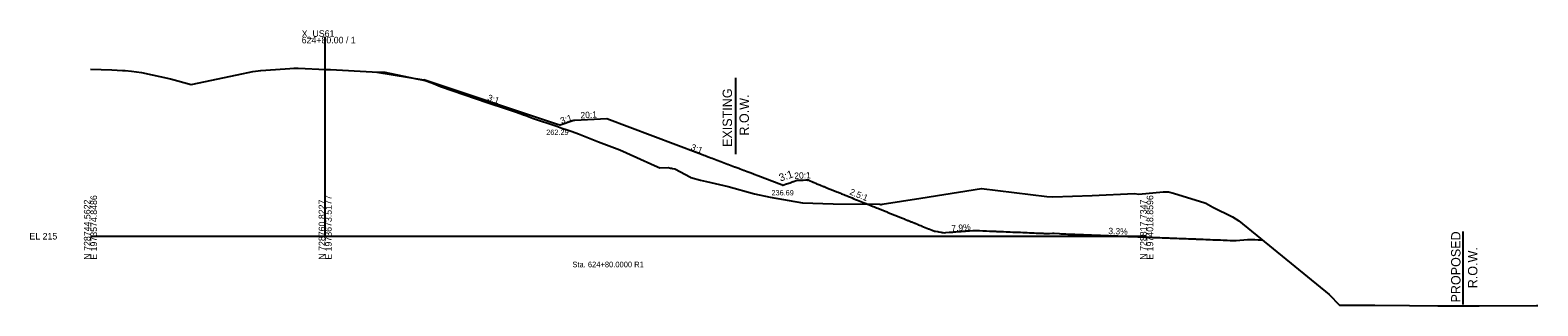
# Model space of a CAD drawing. Extents: x -26 to 630, y -39 to 9098.
# Drawn here: x -26 to 617, y 1970 to 2088 of the extents above; entities that cross this region are included whole.
import ezdxf

# ---------------------------------------------------------------- set-up
doc = ezdxf.new("R2010")
doc.units = 0
for name, color, linetype in [('CONST_DCH', 7, 'Continuous'), ('Default', 7, 'Continuous'), ('Draft_XS_Grid', 7, 'Continuous'), ('Draft_XS_Text', 7, 'Continuous'), ('DTM_X_GROUND', 7, 'Continuous'), ('X_DTM_CONTOURS_MAJOR', 7, 'Continuous'), ('XS_CELL', 7, 'Continuous'), ('XS_P_GROUND', 7, 'Continuous'), ('XS_P_ROW', 7, 'Continuous'), ('XS_P_TX_DCH', 7, 'Continuous'), ('XS_P_TX_FS_BS', 7, 'Continuous'), ('XS_X_ROW', 7, 'Continuous')]:
    doc.layers.add(name, color=color, linetype=linetype)

msp = doc.modelspace()

# ---------------------------------------------------------------- linework, layer by layer
at = {"layer": 'DTM_X_GROUND'}
msp.add_lwpolyline([(0, 2071.16), (9.05, 2070.86), (13.72, 2070.7), (14.81, 2070.61), (17.45, 2070.4), (21.74, 2069.84), (34.08, 2067.05), (42.91, 2064.69), (62.57, 2068.81), (69.11, 2070.18), (72.62, 2070.65), (74.77, 2070.8), (84.88, 2071.51), (86.59, 2071.57), (88.5, 2071.64), (100.31, 2071.11), (102.28, 2071.02), (120, 2070.06), (123.2, 2069.89), (123.41, 2069.89), (125.46, 2069.96), (138.9, 2067.09), (141.96, 2066.49), (143.09, 2066.2), (146.2, 2065.11), (149.2, 2063.86), (168.97, 2057.02), (177.64, 2054.14), (180.66, 2053.14), (183.53, 2052.18), (184.51, 2051.79), (185.52, 2051.39), (188.35, 2050.27), (198.73, 2046.96), (200.81, 2046.05), (202.73, 2045.42), (205.27, 2044.57), (207.88, 2043.65), (216.5, 2040.18), (225.6, 2036.84), (232.83, 2033.61), (240.25, 2030.11), (242.57, 2029.22), (246.18, 2029.32), (247.06, 2029.05), (247.07, 2029.05), (247.11, 2029.04), (247.16, 2029.04), (247.39, 2029), (247.49, 2028.99), (247.93, 2028.93), (249.01, 2028.77), (255.59, 2025.24), (255.81, 2025.09), (259.97, 2023.96), (262.44, 2023.32), (271.66, 2021.21), (282.93, 2018.13), (289.56, 2016.68), (303.36, 2014.22), (316.5, 2013.77), (336.25, 2013.6), (336.7, 2013.49), (336.92, 2013.56), (337.32, 2013.61), (353.8, 2016.2), (379.6, 2020.4), (407.41, 2016.86), (410.06, 2016.82), (426.81, 2017.38), (444.75, 2018.17), (446.65, 2017.98), (457.04, 2018.85), (459.14, 2018.98), (459.28, 2018.97), (461.46, 2018.35), (474.77, 2014.27), (475.2, 2014.04), (478.18, 2012.45), (486.63, 2008.21), (489.23, 2006.55), (527.73, 1975.17), (532.15, 1970.63), (540.97, 1970.65), (545.12, 1970.66), (547.16, 1970.68), (562, 1970.52), (574.07, 1970.38), (591.63, 1970.32), (616.06, 1970.47), (616.67, 1970.42)], dxfattribs=at)
at = {"layer": 'XS_CELL'}
for p, q in [((100, 2000), (100, 2085)), ((0, 2000), (100, 2000)), ((100, 2000), (450, 2000))]:
    msp.add_line(p, q, dxfattribs=at)
at = {"layer": 'XS_P_GROUND'}
for points in [[(122, 2069.95), (142, 2066.62)], [(122, 2069.95), (142, 2066.62)], [(122, 2069.95), (142, 2066.62)], [(305.17, 2023.89), (305.14, 2023.89), (304.94, 2023.88), (304.86, 2023.88), (303.72, 2023.82), (303.67, 2023.82), (302.56, 2023.76), (302.48, 2023.76), (302.31, 2023.75), (301.14, 2023.69), (299.49, 2023.14), (299.44, 2023.12), (298.58, 2022.84), (298.51, 2022.81), (296.11, 2022.01), (296.09, 2022.01), (295.37, 2021.77), (295.35, 2021.76), (295.22, 2021.72), (295.14, 2021.69), (294.66, 2021.87), (294.45, 2021.95), (284.33, 2025.76), (284.29, 2025.78), (282.83, 2026.32), (282.76, 2026.35), (282.43, 2026.47), (281.47, 2026.84), (279.84, 2027.45), (279.73, 2027.49), (278.35, 2028.01), (278.27, 2028.04), (276.85, 2028.58), (276.76, 2028.61), (276.54, 2028.69), (276.2, 2028.82), (274.51, 2029.46), (274.4, 2029.5), (273.02, 2030.02), (272.94, 2030.05), (271.53, 2030.58), (271.44, 2030.62), (268.55, 2031.7), (268.51, 2031.72), (267.06, 2032.27), (267.04, 2032.27), (266.33, 2032.54), (266.29, 2032.55), (264.95, 2033.06), (264.93, 2033.06), (264.3, 2033.3), (264.28, 2033.31), (263.67, 2033.54), (263.63, 2033.55), (262.47, 2033.99), (262.45, 2034), (261.9, 2034.21), (261.88, 2034.21), (261.35, 2034.42), (261.32, 2034.43), (260.29, 2034.81), (259.15, 2035.24), (220, 2049.99), (206.35, 2049.3), (206, 2049.29), (200.15, 2047.34), (200, 2047.29), (198.57, 2047.76), (142, 2066.62)], [(305.34, 2023.9), (305.25, 2023.9)], [(305.43, 2023.9), (305.34, 2023.9)], [(305.43, 2023.9), (305.7, 2023.92)], [(305.71, 2023.92), (305.7, 2023.92)], [(305.74, 2023.92), (305.73, 2023.92), (305.71, 2023.92)], [(306, 2023.93), (305.74, 2023.92)], [(306, 2023.93), (306, 2023.93), (306, 2023.93), (306, 2023.93), (306, 2023.93), (307.93, 2023.01), (308.02, 2022.97), (309.37, 2022.42), (309.53, 2022.36), (310.82, 2021.84), (311.03, 2021.75), (312.27, 2021.25), (312.54, 2021.15), (313.72, 2020.67), (314.04, 2020.54), (315.16, 2020.09), (315.54, 2019.94), (316.61, 2019.5), (317.04, 2019.33), (318.06, 2018.92), (318.54, 2018.73), (319.51, 2018.34), (320.03, 2018.13), (320.95, 2017.75), (321.53, 2017.52), (322.4, 2017.17), (323.02, 2016.92), (323.85, 2016.59), (324.51, 2016.32), (325.3, 2016), (326, 2015.72), (326.74, 2015.42), (327.49, 2015.12), (328.19, 2014.84), (328.98, 2014.52), (329.64, 2014.25), (330.47, 2013.92), (331.09, 2013.67), (331.95, 2013.32), (332.53, 2013.09), (333.44, 2012.72), (333.98, 2012.5), (334.92, 2012.12), (335.43, 2011.92), (336.41, 2011.52), (336.88, 2011.33), (337.89, 2010.93), (338.32, 2010.75), (339.37, 2010.33), (339.77, 2010.17), (340.85, 2009.73), (341.22, 2009.58), (342.33, 2009.13), (342.67, 2009), (343.81, 2008.54), (344.11, 2008.42), (345.29, 2007.94), (345.56, 2007.83), (346.77, 2007.35), (347.01, 2007.25), (348.25, 2006.75), (348.46, 2006.67), (349.72, 2006.16), (349.9, 2006.08), (351.2, 2005.56), (351.35, 2005.5), (352.67, 2004.97), (352.8, 2004.92), (354.15, 2004.37), (354.25, 2004.33), (355.62, 2003.78), (355.69, 2003.75), (357.1, 2003.18), (357.14, 2003.16), (358.57, 2002.59), (358.59, 2002.58), (359.58, 2002.18), (360.04, 2002.11), (360.99, 2001.95), (361.48, 2001.87), (362.5, 2001.71), (362.93, 2001.64), (363.14, 2001.61), (363.73, 2001.51)], [(363.73, 2001.51), (364.38, 2001.56), (364.46, 2001.57), (365.83, 2001.67), (366.1, 2001.7), (367.27, 2001.79), (367.74, 2001.83), (368.72, 2001.9), (369.38, 2001.95), (370.17, 2002.02), (371.02, 2002.08), (371.62, 2002.13), (372.65, 2002.21), (373.06, 2002.25), (374.29, 2002.34), (374.51, 2002.36), (375.93, 2002.47), (375.96, 2002.47), (376.18, 2002.49), (377.38, 2002.44), (377.41, 2002.44), (378.8, 2002.38), (378.85, 2002.38), (380.23, 2002.32), (380.3, 2002.32), (381.65, 2002.26), (381.75, 2002.26), (383.07, 2002.2), (383.2, 2002.2), (384.49, 2002.14), (384.64, 2002.14), (385.91, 2002.09), (386.09, 2002.08), (387.34, 2002.03), (387.54, 2002.02), (388.76, 2001.97), (388.98, 2001.96), (390.18, 2001.91), (390.43, 2001.9), (391.6, 2001.85), (391.88, 2001.84), (393.03, 2001.79), (393.33, 2001.78), (394.45, 2001.73), (394.77, 2001.72), (395.87, 2001.67), (396.22, 2001.66), (397.3, 2001.61), (397.67, 2001.6), (398.72, 2001.55), (399.12, 2001.54), (400.15, 2001.49), (400.56, 2001.47), (401.57, 2001.43), (402.01, 2001.41), (402.99, 2001.37), (403.46, 2001.35), (404.42, 2001.31), (404.91, 2001.29), (405.84, 2001.25), (406.35, 2001.23), (407.27, 2001.2), (407.8, 2001.17), (408.26, 2001.15), (408.54, 2001.14), (409.86, 2001.26), (410.56, 2001.27), (412.79, 2001.19), (412.79, 2001.19), (412.79, 2001.19), (412.79, 2001.19), (412.79, 2001.19), (413.5, 2001.04), (414.14, 2001.02), (414.94, 2000.99), (415.6, 2000.96), (416.38, 2000.93), (417.06, 2000.91), (417.82, 2000.88), (418.53, 2000.85), (419.26, 2000.82), (419.99, 2000.79), (420.7, 2000.76), (421.45, 2000.74), (422.14, 2000.71), (422.91, 2000.68), (423.58, 2000.65), (424.38, 2000.62), (425.02, 2000.6), (425.84, 2000.56), (426.46, 2000.54), (427.3, 2000.51), (427.9, 2000.48), (428.76, 2000.45), (429.35, 2000.43), (430.23, 2000.39), (430.81, 2000.37), (431.69, 2000.34), (432.26, 2000.32), (433.15, 2000.28), (433.72, 2000.26), (434.61, 2000.22), (435.17, 2000.2), (436.08, 2000.17), (436.63, 2000.15), (437.54, 2000.11), (438.08, 2000.09), (439, 2000.05), (439.54, 2000.03), (440.46, 2000), (441, 1999.98), (441.92, 1999.94), (442.45, 1999.92), (443.39, 1999.88), (443.91, 1999.86), (444.85, 1999.83), (445.37, 1999.81), (446.31, 1999.77), (446.83, 1999.75), (447.77, 1999.71), (448.28, 1999.69), (449.24, 1999.65), (449.74, 1999.64), (450.7, 1999.6), (451.2, 1999.58), (452.16, 1999.54), (452.66, 1999.52), (453.62, 1999.48), (454.12, 1999.46), (455.09, 1999.43), (455.58, 1999.41), (456.55, 1999.37), (457.04, 1999.35), (458.01, 1999.31), (458.5, 1999.29), (459.47, 1999.26), (459.98, 1999.24), (460.94, 1999.2), (461.43, 1999.18), (462.4, 1999.14), (462.88, 1999.12), (463.86, 1999.09), (464.33, 1999.07), (465.32, 1999.03), (466.34, 1998.99), (466.78, 1998.97), (467.82, 1998.93), (468.25, 1998.92), (469.3, 1998.87), (469.71, 1998.86), (470.78, 1998.82), (471.17, 1998.8), (472.26, 1998.76), (472.63, 1998.74), (473.74, 1998.7), (474.1, 1998.69), (475.22, 1998.64), (475.56, 1998.63), (476.7, 1998.59), (477.02, 1998.57), (478.18, 1998.53), (478.48, 1998.52), (479.67, 1998.47), (479.95, 1998.46), (481.15, 1998.41), (481.41, 1998.4), (482.63, 1998.36), (482.87, 1998.35), (484.12, 1998.3), (484.33, 1998.29), (485.6, 1998.24), (485.79, 1998.23), (487.08, 1998.18), (487.26, 1998.18), (488.03, 1998.15), (488.13, 1998.14), (492.96, 1998.65), (493.02, 1998.65), (494.47, 1998.61), (494.54, 1998.61), (496, 1998.56), (496.05, 1998.56), (497.54, 1998.52), (497.56, 1998.51), (499.07, 1998.47), (499.07, 1998.47), (499.14, 1998.47)]]:
    msp.add_lwpolyline(points, dxfattribs=at)
at = {"layer": 'XS_P_ROW'}
msp.add_line((584.73, 2001.97), (584.73, 1970.96), dxfattribs=at)
at = {"layer": 'XS_X_ROW'}
msp.add_line((275, 2035), (275, 2067.48), dxfattribs=at)

# ---------------------------------------------------------------- texts
at = {"layer": 'CONST_DCH'}
for p in [(306, 2023.93), (376.18, 2002.49)]:
    msp.add_text('X', height=0.001, dxfattribs=at).set_placement(p)
at = {"layer": 'Default'}
for p in [(199.96, 2047.23), (295.1, 2021.63), (340.69, 2014.09)]:
    msp.add_text('X', height=0.12, dxfattribs=at).set_placement(p)
at = {"layer": 'Draft_XS_Grid'}
msp.add_text('-', height=0.0001, dxfattribs=at).set_placement((0, 2000))
at = {"layer": 'Draft_XS_Text'}
msp.add_text('Sta. 624+80.0000 R1', height=2.4, dxfattribs=at).set_placement((205.34, 1986.75))
at = {"layer": 'X_DTM_CONTOURS_MAJOR'}
for height, p in [(0.12, (121.96, 2069.89)), (0.12, (121.96, 2069.89)), (0.001, (122, 2069.95)), (0.12, (141.96, 2066.56)), (0.12, (141.96, 2066.56)), (0.001, (142, 2066.62)), (0.12, (205.96, 2049.23)), (0.12, (219.96, 2049.93)), (0.12, (265.05, 2033.5)), (0.12, (301.1, 2023.63)), (0.12, (301.1, 2023.63)), (0.001, (301.14, 2023.69)), (0.12, (315.1, 2024.33))]:
    msp.add_text('X', height=height, dxfattribs=at).set_placement(p)
at = {"layer": 'XS_CELL'}
for s, p in [('X_US61', (90, 2085)), ('624+80.00 / 1', (90, 2082.2)), ('EL 215', (-26, 1998.6))]:
    msp.add_text(s, height=2.8, dxfattribs=at).set_placement(p)
for s, p in [('E 1973574.8486', (2.8, 1990)), ('E 1973673.5177', (102.8, 1990)), ('E 1974018.8596', (452.8, 1990)), ('N 728744.5622', (0, 1990)), ('N 728760.8227', (100, 1990)), ('N 728817.7347', (450, 1990))]:
    msp.add_text(s, height=2.8, rotation=90, dxfattribs=at).set_placement(p)
at = {"layer": 'XS_P_ROW'}
for s, p in [('EXISTING', (273.33, 2038.04)), ('R.O.W.', (280.53, 2042.89)), ('PROPOSED', (583.71, 1971.75)), ('R.O.W.', (590.91, 1977.82))]:
    msp.add_text(s, height=4, rotation=90, dxfattribs=at).set_placement(p)
at = {"layer": 'XS_P_TX_DCH'}
for s, p in [('262.29', (194.21, 2043.19)), ('236.69', (290.16, 2017.41))]:
    msp.add_text(s, height=2.25, dxfattribs=at).set_placement(p)
at = {"layer": 'XS_P_TX_FS_BS'}
for s, height, rotation, p in [('3:1', 2.7, 341.56505, (168.92, 2057.96)), ('3:1', 2.7, 18.43495, (200.73, 2047.85)), ('20:1', 2.7, 2.86247, (208.83, 2050.2)), ('3:1', 2.7, 339.36327, (255.53, 2036.93)), ('3:1', 3.24, 18.43501, (293.96, 2023.27)), ('3:1', 3.24, 18.43501, (293.96, 2023.27)), ('20:1', 2.7, 2.86247, (299.94, 2024.4)), ('2.5:1', 2.7, 337.90642, (323.17, 2017.91)), ('7.9%', 2.7, 4.50802, (366.91, 2001.98)), ('3.3%', 2.7, 358.12576, (433.65, 2000.91))]:
    msp.add_text(s, height=height, rotation=rotation, dxfattribs=at).set_placement(p)

doc.saveas('drawing.dxf')
